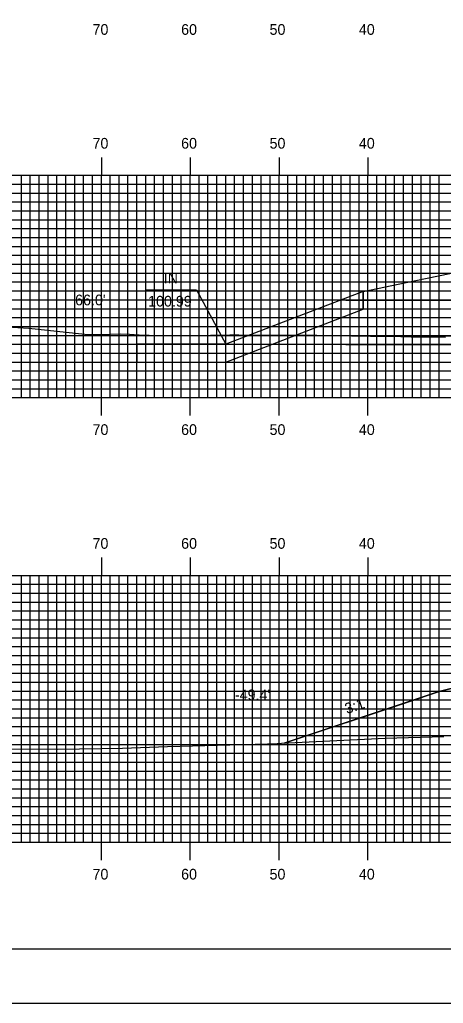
# Model space of a CAD drawing. Extents: x 1765726 to 1766069, y 442591 to 442811.
# Drawn here: x 1765812.7 to 1765860.4, y 442590.5 to 442701.2 of the extents above; entities that cross this region are included whole.
import ezdxf

# ---------------------------------------------------------------- set-up
doc = ezdxf.new("R2010")
doc.units = 0
for name, color, linetype in [('ANNOTATION', 7, 'Continuous'), ('BORDER', 7, 'Continuous'), ('D_Drainage_Culvert', 7, 'Continuous'), ('D_Roadway_Centerline', 7, 'Continuous'), ('D_Roadway_FinishedGrade', 7, 'Continuous'), ('D_Roadway_SlopeLines', 7, 'Continuous'), ('D_Roadway_SubGrade', 7, 'Continuous'), ('D_Text_Standard', 7, 'Continuous'), ('H_V ANNOTATION', 7, 'Continuous'), ('MAJOR', 7, 'Continuous'), ('MINOR', 7, 'Continuous'), ('PLOT BOUNDARY', 7, 'Continuous'), ('S_Roadway_Centerline', 7, 'Continuous')]:
    doc.layers.add(name, color=color, linetype=linetype)

msp = doc.modelspace()

# ---------------------------------------------------------------- linework, layer by layer
at = {"layer": 'ANNOTATION'}
msp.add_lwpolyline([(1765826.87, 442670.78), (1765832.57, 442670.78), (1765835.88, 442664.67)], dxfattribs=at)
at = {"layer": 'BORDER'}
msp.add_lwpolyline([(1765742.28, 442596.67), (1766062.28, 442596.67), (1766062.28, 442806.67), (1765742.28, 442806.67)], close=True, dxfattribs=at)
at = {"layer": 'D_Drainage_Culvert'}
for p, q in [((1765835.88, 442664.66), (1765835.89, 442669.66)), ((1765835.89, 442669.66), (1765947.89, 442669.37)), ((1765835.88, 442664.66), (1765947.87, 442664.37))]:
    msp.add_line(p, q, dxfattribs=at)
at = {"layer": 'D_Roadway_Centerline'}
msp.add_lwpolyline([(1765842.47, 442619.81), (1765856.2, 442624.39), (1765859.88, 442625.62), (1765861.71, 442626.08), (1765861.72, 442626.08), (1765866.81, 442627.35), (1765871.88, 442628.62), (1765871.89, 442628.62), (1765879.88, 442628.94), (1765891.88, 442628.67), (1765903.88, 442628.41), (1765903.88, 442628.41), (1765911.88, 442628.09), (1765911.88, 442628.09), (1765917.58, 442626.67), (1765922.05, 442625.55), (1765922.06, 442625.55), (1765922.07, 442625.55), (1765942.9, 442620.34)], dxfattribs=at)
at = {"layer": 'D_Roadway_FinishedGrade'}
for p, q in [((1765851.33, 442670.62), (1765856.17, 442671.63)), ((1765851.33, 442670.62), (1765835.88, 442664.67)), ((1765851.33, 442670.62), (1765835.88, 442664.67)), ((1765851.33, 442670.62), (1765851.33, 442668.62)), ((1765851.33, 442668.62), (1765851.33, 442670.62)), ((1765835.88, 442662.66), (1765851.33, 442668.62)), ((1765835.88, 442662.66), (1765851.33, 442668.62)), ((1765825.88, 442665.68), (1765947.88, 442665.37)), ((1765825.88, 442664.67), (1765825.88, 442665.68)), ((1765835.88, 442664.67), (1765825.88, 442664.67)), ((1765835.88, 442664.67), (1765825.88, 442664.67))]:
    msp.add_line(p, q, dxfattribs=at)
msp.add_lwpolyline([(1765825.88, 442664.67), (1765825.88, 442662.67), (1765835.88, 442662.66)], dxfattribs=at)
msp.add_lwpolyline([(1765825.88, 442664.67), (1765825.88, 442662.67), (1765835.88, 442662.66)], dxfattribs=at)
at = {"layer": 'D_Roadway_SlopeLines'}
msp.add_lwpolyline([(1765871.88, 442628.62), (1765859.88, 442625.62), (1765842.47, 442619.81)], dxfattribs=at)
at = {"layer": 'D_Roadway_SubGrade'}
msp.add_lwpolyline([(1765877.67, 442671.87), (1765856.17, 442671.63), (1765868.2, 442674.1), (1765868.2, 442673.85), (1765877.67, 442674.12), (1765891.88, 442673.78), (1765906.11, 442673.44), (1765915.6, 442673.06), (1765915.6, 442673.31), (1765930.53, 442670.66), (1765906.11, 442671.19), (1765891.88, 442671.53)], close=True, dxfattribs=at)
at = {"layer": 'MAJOR'}
for p, q in [((1765821.88, 442685.67), (1765821.88, 442683.67)), ((1765831.88, 442685.67), (1765831.88, 442683.67)), ((1765841.88, 442685.67), (1765841.88, 442683.67)), ((1765851.88, 442685.67), (1765851.88, 442683.67)), ((1765751.88, 442683.67), (1766031.88, 442683.67)), ((1765751.88, 442683.67), (1766031.88, 442683.67)), ((1765821.88, 442658.67), (1765821.88, 442683.67)), ((1765831.88, 442658.67), (1765831.88, 442683.67)), ((1765841.88, 442658.67), (1765841.88, 442683.67)), ((1765851.88, 442658.67), (1765851.88, 442683.67)), ((1765751.88, 442678.67), (1766031.88, 442678.67)), ((1765751.88, 442673.67), (1766031.88, 442673.67)), ((1765751.88, 442668.67), (1766031.88, 442668.67)), ((1765751.88, 442663.67), (1766031.88, 442663.67)), ((1765751.88, 442658.67), (1766031.88, 442658.67)), ((1765751.88, 442658.67), (1766031.88, 442658.67)), ((1765821.88, 442656.66), (1765821.88, 442658.67)), ((1765831.88, 442656.66), (1765831.88, 442658.67)), ((1765841.88, 442656.66), (1765841.88, 442658.67)), ((1765851.88, 442656.66), (1765851.88, 442658.67)), ((1765821.88, 442640.67), (1765821.88, 442638.67)), ((1765831.88, 442640.67), (1765831.88, 442638.67)), ((1765841.88, 442640.67), (1765841.88, 442638.67)), ((1765851.88, 442640.67), (1765851.88, 442638.67)), ((1765751.88, 442638.67), (1766031.88, 442638.67)), ((1765751.88, 442638.67), (1766031.88, 442638.67)), ((1765821.88, 442608.67), (1765821.88, 442638.67)), ((1765831.88, 442608.67), (1765831.88, 442638.67)), ((1765841.88, 442608.67), (1765841.88, 442638.67)), ((1765851.88, 442608.67), (1765851.88, 442638.67)), ((1765751.88, 442633.67), (1766031.88, 442633.67)), ((1765751.88, 442628.67), (1766031.88, 442628.67)), ((1765751.88, 442623.67), (1766031.88, 442623.67)), ((1765751.88, 442618.67), (1766031.88, 442618.67)), ((1765751.88, 442613.67), (1766031.88, 442613.67)), ((1765751.88, 442608.67), (1766031.88, 442608.67)), ((1765751.88, 442608.67), (1766031.88, 442608.67)), ((1765821.88, 442606.66), (1765821.88, 442608.67)), ((1765831.88, 442606.66), (1765831.88, 442608.67)), ((1765841.88, 442606.66), (1765841.88, 442608.67)), ((1765851.88, 442606.66), (1765851.88, 442608.67))]:
    msp.add_line(p, q, dxfattribs=at)
at = {"layer": 'MINOR'}
for p, q in [((1765812.88, 442658.67), (1765812.88, 442683.67)), ((1765813.88, 442658.67), (1765813.88, 442683.67)), ((1765814.88, 442658.67), (1765814.88, 442683.67)), ((1765815.88, 442658.67), (1765815.88, 442683.67)), ((1765816.88, 442658.67), (1765816.88, 442683.67)), ((1765817.88, 442658.67), (1765817.88, 442683.67)), ((1765818.88, 442658.67), (1765818.88, 442683.67)), ((1765819.88, 442658.67), (1765819.88, 442683.67)), ((1765820.88, 442658.67), (1765820.88, 442683.67)), ((1765822.88, 442658.67), (1765822.88, 442683.67)), ((1765823.88, 442658.67), (1765823.88, 442683.67)), ((1765824.88, 442658.67), (1765824.88, 442683.67)), ((1765825.88, 442658.67), (1765825.88, 442683.67)), ((1765826.88, 442658.67), (1765826.88, 442683.67)), ((1765827.88, 442658.67), (1765827.88, 442683.67)), ((1765828.88, 442658.67), (1765828.88, 442683.67)), ((1765829.88, 442658.67), (1765829.88, 442683.67)), ((1765830.88, 442658.67), (1765830.88, 442683.67)), ((1765832.88, 442658.67), (1765832.88, 442683.67)), ((1765833.88, 442658.67), (1765833.88, 442683.67)), ((1765834.88, 442658.67), (1765834.88, 442683.67)), ((1765835.88, 442658.67), (1765835.88, 442683.67)), ((1765836.88, 442658.67), (1765836.88, 442683.67)), ((1765837.88, 442658.67), (1765837.88, 442683.67)), ((1765838.88, 442658.67), (1765838.88, 442683.67)), ((1765839.88, 442658.67), (1765839.88, 442683.67)), ((1765840.88, 442658.67), (1765840.88, 442683.67)), ((1765842.88, 442658.67), (1765842.88, 442683.67)), ((1765843.88, 442658.67), (1765843.88, 442683.67)), ((1765844.88, 442658.67), (1765844.88, 442683.67)), ((1765845.88, 442658.67), (1765845.88, 442683.67)), ((1765846.88, 442658.67), (1765846.88, 442683.67)), ((1765847.88, 442658.67), (1765847.88, 442683.67)), ((1765848.88, 442658.67), (1765848.88, 442683.67)), ((1765849.88, 442658.67), (1765849.88, 442683.67)), ((1765850.88, 442658.67), (1765850.88, 442683.67)), ((1765852.88, 442658.67), (1765852.88, 442683.67)), ((1765853.88, 442658.67), (1765853.88, 442683.67)), ((1765854.88, 442658.67), (1765854.88, 442683.67)), ((1765855.88, 442658.67), (1765855.88, 442683.67)), ((1765856.88, 442658.67), (1765856.88, 442683.67)), ((1765857.88, 442658.67), (1765857.88, 442683.67)), ((1765858.88, 442658.67), (1765858.88, 442683.67)), ((1765859.88, 442658.67), (1765859.88, 442683.67)), ((1765751.88, 442682.67), (1766031.88, 442682.67)), ((1765751.88, 442681.67), (1766031.88, 442681.67)), ((1765751.88, 442680.67), (1766031.88, 442680.67)), ((1765751.88, 442679.67), (1766031.88, 442679.67)), ((1765751.88, 442677.67), (1766031.88, 442677.67)), ((1765751.88, 442676.67), (1766031.88, 442676.67)), ((1765751.88, 442675.67), (1766031.88, 442675.67)), ((1765751.88, 442674.67), (1766031.88, 442674.67)), ((1765751.88, 442672.67), (1766031.88, 442672.67)), ((1765751.88, 442671.67), (1766031.88, 442671.67)), ((1765751.88, 442670.67), (1766031.88, 442670.67)), ((1765751.88, 442669.67), (1766031.88, 442669.67)), ((1765751.88, 442667.67), (1766031.88, 442667.67)), ((1765751.88, 442666.67), (1766031.88, 442666.67)), ((1765751.88, 442665.67), (1766031.88, 442665.67)), ((1765751.88, 442664.67), (1766031.88, 442664.67)), ((1765751.88, 442662.67), (1766031.88, 442662.67)), ((1765751.88, 442661.67), (1766031.88, 442661.67)), ((1765751.88, 442660.67), (1766031.88, 442660.67)), ((1765751.88, 442659.67), (1766031.88, 442659.67)), ((1765812.88, 442608.67), (1765812.88, 442638.67)), ((1765813.88, 442608.67), (1765813.88, 442638.67)), ((1765814.88, 442608.67), (1765814.88, 442638.67)), ((1765815.88, 442608.67), (1765815.88, 442638.67)), ((1765816.88, 442608.67), (1765816.88, 442638.67)), ((1765817.88, 442608.67), (1765817.88, 442638.67)), ((1765818.88, 442608.67), (1765818.88, 442638.67)), ((1765819.88, 442608.67), (1765819.88, 442638.67)), ((1765820.88, 442608.67), (1765820.88, 442638.67)), ((1765822.88, 442608.67), (1765822.88, 442638.67)), ((1765823.88, 442608.67), (1765823.88, 442638.67)), ((1765824.88, 442608.67), (1765824.88, 442638.67)), ((1765825.88, 442608.67), (1765825.88, 442638.67)), ((1765826.88, 442608.67), (1765826.88, 442638.67)), ((1765827.88, 442608.67), (1765827.88, 442638.67)), ((1765828.88, 442608.67), (1765828.88, 442638.67)), ((1765829.88, 442608.67), (1765829.88, 442638.67)), ((1765830.88, 442608.67), (1765830.88, 442638.67)), ((1765832.88, 442608.67), (1765832.88, 442638.67)), ((1765833.88, 442608.67), (1765833.88, 442638.67)), ((1765834.88, 442608.67), (1765834.88, 442638.67)), ((1765835.88, 442608.67), (1765835.88, 442638.67)), ((1765836.88, 442608.67), (1765836.88, 442638.67)), ((1765837.88, 442608.67), (1765837.88, 442638.67)), ((1765838.88, 442608.67), (1765838.88, 442638.67)), ((1765839.88, 442608.67), (1765839.88, 442638.67)), ((1765840.88, 442608.67), (1765840.88, 442638.67)), ((1765842.88, 442608.67), (1765842.88, 442638.67)), ((1765843.88, 442608.67), (1765843.88, 442638.67)), ((1765844.88, 442608.67), (1765844.88, 442638.67)), ((1765845.88, 442608.67), (1765845.88, 442638.67)), ((1765846.88, 442608.67), (1765846.88, 442638.67)), ((1765847.88, 442608.67), (1765847.88, 442638.67)), ((1765848.88, 442608.67), (1765848.88, 442638.67)), ((1765849.88, 442608.67), (1765849.88, 442638.67)), ((1765850.88, 442608.67), (1765850.88, 442638.67)), ((1765852.88, 442608.67), (1765852.88, 442638.67)), ((1765853.88, 442608.67), (1765853.88, 442638.67)), ((1765854.88, 442608.67), (1765854.88, 442638.67)), ((1765855.88, 442608.67), (1765855.88, 442638.67)), ((1765856.88, 442608.67), (1765856.88, 442638.67)), ((1765857.88, 442608.67), (1765857.88, 442638.67)), ((1765858.88, 442608.67), (1765858.88, 442638.67)), ((1765859.88, 442608.67), (1765859.88, 442638.67)), ((1765751.88, 442637.67), (1766031.88, 442637.67)), ((1765751.88, 442636.67), (1766031.88, 442636.67)), ((1765751.88, 442635.67), (1766031.88, 442635.67)), ((1765751.88, 442634.67), (1766031.88, 442634.67)), ((1765751.88, 442632.67), (1766031.88, 442632.67)), ((1765751.88, 442631.67), (1766031.88, 442631.67)), ((1765751.88, 442630.67), (1766031.88, 442630.67)), ((1765751.88, 442629.67), (1766031.88, 442629.67)), ((1765751.88, 442627.67), (1766031.88, 442627.67)), ((1765751.88, 442626.67), (1766031.88, 442626.67)), ((1765751.88, 442625.67), (1766031.88, 442625.67)), ((1765751.88, 442624.67), (1766031.88, 442624.67)), ((1765751.88, 442622.67), (1766031.88, 442622.67)), ((1765751.88, 442621.67), (1766031.88, 442621.67)), ((1765751.88, 442620.67), (1766031.88, 442620.67)), ((1765751.88, 442619.67), (1766031.88, 442619.67)), ((1765751.88, 442617.67), (1766031.88, 442617.67)), ((1765751.88, 442616.67), (1766031.88, 442616.67)), ((1765751.88, 442615.67), (1766031.88, 442615.67)), ((1765751.88, 442614.67), (1766031.88, 442614.67)), ((1765751.88, 442612.67), (1766031.88, 442612.67)), ((1765751.88, 442611.67), (1766031.88, 442611.67)), ((1765751.88, 442610.67), (1766031.88, 442610.67)), ((1765751.88, 442609.67), (1766031.88, 442609.67))]:
    msp.add_line(p, q, dxfattribs=at)
at = {"layer": 'PLOT BOUNDARY'}
msp.add_lwpolyline([(1765726.1, 442590.55), (1766066.1, 442590.55), (1766066.1, 442810.55), (1765726.1, 442810.55)], close=True, dxfattribs=at)
at = {"layer": 'S_Roadway_Centerline'}
for points in [[(1765811.26, 442666.63), (1765813.72, 442666.48), (1765820.04, 442665.79), (1765821.58, 442665.75), (1765824.05, 442665.83), (1765825.05, 442665.79), (1765826.13, 442665.74), (1765827.27, 442665.7), (1765828.41, 442665.67), (1765829.47, 442665.66), (1765830.63, 442665.66), (1765831.82, 442665.66), (1765833.01, 442665.67), (1765834.17, 442665.68), (1765836.34, 442665.71), (1765837.34, 442665.73), (1765840.87, 442665.69), (1765842.17, 442665.69), (1765843.36, 442665.7), (1765844.41, 442665.69), (1765846.14, 442665.68), (1765848.01, 442665.65), (1765850.02, 442665.63), (1765852.17, 442665.59), (1765854.41, 442665.56), (1765856.75, 442665.52), (1765858.83, 442665.51), (1765860.6, 442665.48)], [(1765806.02, 442619.18), (1765816.98, 442619.14), (1765824.26, 442619.24), (1765829.31, 442619.42), (1765840.56, 442619.74), (1765841.66, 442619.78), (1765842.15, 442619.8), (1765853.82, 442620.38), (1765860.41, 442620.57)]]:
    msp.add_lwpolyline(points, dxfattribs=at)

# ---------------------------------------------------------------- texts
at = {"layer": 'ANNOTATION'}
for s, p in [('IN', (1765828.9, 442671.51)), ('100.99', (1765827.14, 442668.91))]:
    msp.add_text(s, height=1.2, dxfattribs=at).set_placement(p)
msp.add_text('3:1', height=1.2, rotation=18.4333, dxfattribs=at).set_placement((1765849.51, 442623.07))
at = {"layer": 'D_Text_Standard'}
for s, p in [("66.0'", (1765818.93, 442669.05)), ("-49.4'", (1765836.91, 442624.64))]:
    msp.add_text(s, height=1.2, dxfattribs=at).set_placement(p)
at = {"layer": 'H_V ANNOTATION'}
for s, p in [('70', (1765820.89, 442699.47)), ('60', (1765830.86, 442699.47)), ('50', (1765840.81, 442699.47)), ('40', (1765850.86, 442699.47)), ('70', (1765820.89, 442686.67)), ('60', (1765830.86, 442686.67)), ('50', (1765840.81, 442686.67)), ('40', (1765850.86, 442686.67)), ('70', (1765820.89, 442654.47)), ('60', (1765830.86, 442654.47)), ('50', (1765840.81, 442654.47)), ('40', (1765850.86, 442654.47)), ('70', (1765820.89, 442641.67)), ('60', (1765830.86, 442641.67)), ('50', (1765840.81, 442641.67)), ('40', (1765850.86, 442641.67)), ('70', (1765820.89, 442604.47)), ('60', (1765830.86, 442604.47)), ('50', (1765840.81, 442604.47)), ('40', (1765850.86, 442604.47))]:
    msp.add_text(s, height=1.2, dxfattribs=at).set_placement(p)

doc.saveas('drawing.dxf')
